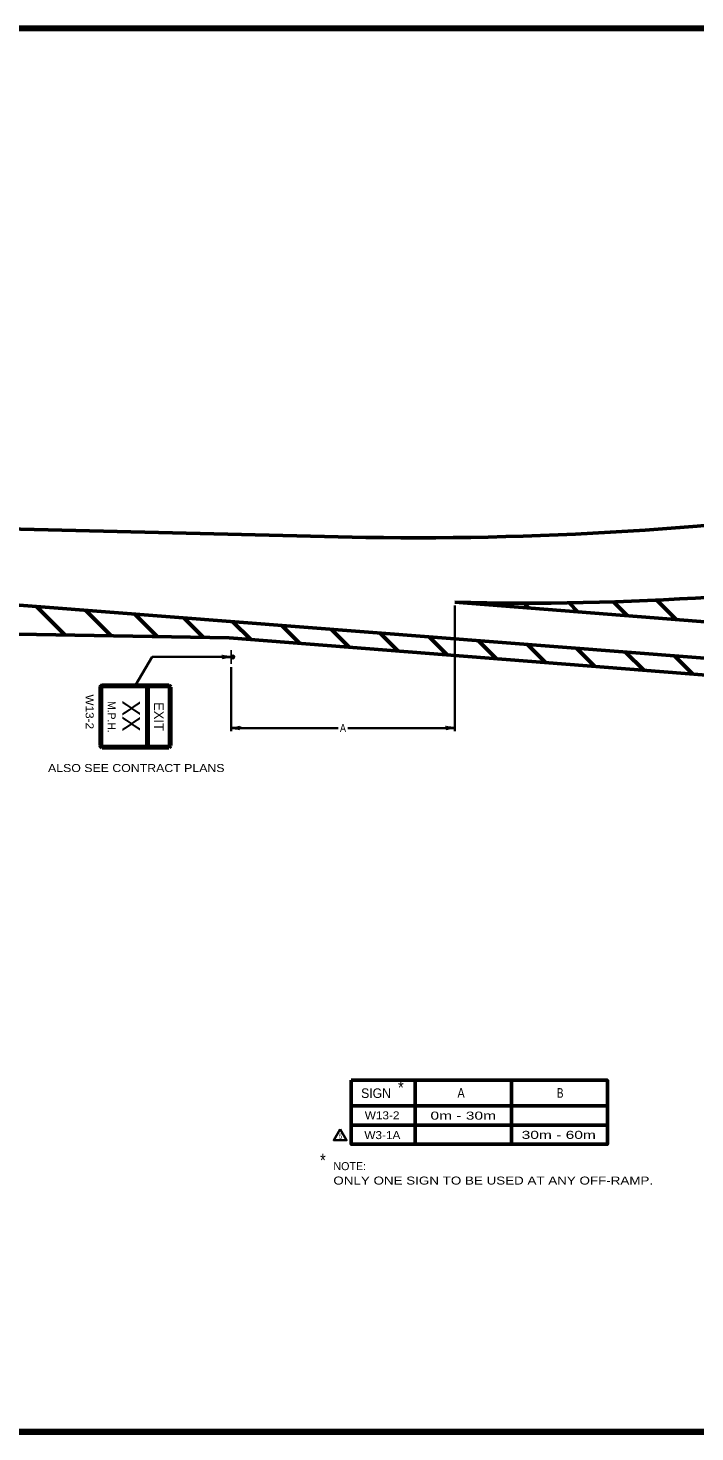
# Model space of a CAD drawing. Extents: x -371 to 484, y -338 to 206.
# Drawn here: x -83 to 167, y -326 to 200 of the extents above; entities that cross this region are included whole.
import ezdxf
from ezdxf.enums import TextEntityAlignment as Align

# ---------------------------------------------------------------- set-up
doc = ezdxf.new("R2010")
doc.units = 0
doc.layers.add('1', color=7, linetype='Continuous', lineweight=53)
doc.layers.add('4', color=7, linetype='Continuous', lineweight=25)
doc.layers.add('2', color=7, linetype='Continuous')

msp = doc.modelspace()

# ---------------------------------------------------------------- hatches: boundary and pattern name
at = {"layer": '4'}
msp.add_hatch(color=256, dxfattribs=at).paths.add_polyline_path([(-6.38, -36.735, 1), (-6.38, -35.423, 1)])

# ---------------------------------------------------------------- linework, layer by layer
at = {"layer": '1'}
for p, q in [((-288.756, 16.515), (43.484, 8.747)), ((76.814, -15.591), (456.428, -45.449)), ((86.227, -16.332), (85.575, -15.679)), ((123.066, -19.229), (119.501, -15.664)), ((141.485, -20.678), (136.155, -15.347)), ((159.905, -22.127), (152.429, -14.65)), ((-69.234, -27.852), (-79.901, -17.185)), ((-51.961, -28.155), (-61.511, -18.605)), ((-34.687, -28.457), (-43.12, -20.024)), ((104.647, -17.78), (102.717, -15.85)), ((-17.414, -28.76), (-24.73, -21.444)), ((0.361, -29.565), (-6.34, -22.863)), ((18.771, -31.004), (12.05, -24.283)), ((37.181, -32.443), (30.44, -25.703)), ((55.591, -33.882), (48.831, -27.122)), ((74, -35.321), (67.221, -28.542)), ((92.41, -36.761), (85.611, -29.962)), ((110.82, -38.2), (104.001, -31.381)), ((129.23, -39.639), (122.391, -32.801)), ((147.639, -41.078), (140.781, -34.22)), ((166.049, -42.517), (159.172, -35.64)), ((61.998, -218.715), (61.998, -194.715)), ((97.998, -218.715), (97.998, -194.715)), ((37.998, -204.315), (133.998, -204.315)), ((37.998, -211.514), (133.998, -211.514))]:
    msp.add_line(p, q, dxfattribs=at)
at = {"layer": '1', "lineweight": 35}
for p, q in [((76.814, -16.791), (76.814, -63.9)), ((-42.878, -46.653), (-36.641, -36.079)), ((-7.02, -36.079), (-36.641, -36.079)), ((-7.02, -39.839), (-7.02, -63.9)), ((-7.02, -62.7), (33.097, -62.7)), ((36.697, -62.7), (76.814, -62.7))]:
    msp.add_line(p, q, dxfattribs=at)
at = {"layer": '1', "lineweight": 13}
for p, q in [((-56.038, -69.464), (-56.038, -47.238)), ((-55.512, -46.653), (-30.243, -46.653)), ((-29.717, -47.238), (-29.717, -69.464)), ((-30.243, -70.049), (-55.512, -70.049))]:
    msp.add_line(p, q, dxfattribs=at)
at = {"layer": '1', "lineweight": 70}
for p, q in [((-55.358, -46.872), (-30.397, -46.872)), ((-38.349, -46.872), (-38.349, -69.83)), ((-55.841, -69.294), (-55.841, -47.408)), ((-29.914, -47.408), (-29.914, -69.294)), ((-30.397, -69.83), (-55.358, -69.83))]:
    msp.add_line(p, q, dxfattribs=at)
at = {"layer": '1', "lineweight": 158}
msp.add_line((477.495, -326.494), (-314.105, -326.494), dxfattribs=at)
msp.add_lwpolyline([(477.495, 199.606), (-314.205, 199.506), (-314.105, -326.494)], dxfattribs=at)
at = {"layer": '1'}
for points in [[(-289.357, -11.407), (-102.62, -15.431), (458.068, -58.713)], [(460.106, -65.505), (-7.77, -28.929), (-289.578, -23.989)]]:
    msp.add_lwpolyline(points, dxfattribs=at)
msp.add_lwpolyline([(37.998, -194.715), (133.998, -194.715), (133.998, -218.715), (37.998, -218.715)], close=True, dxfattribs=at)
at = {"layer": '1', "lineweight": 35}
msp.add_lwpolyline([(33.875, -213.023), (31.475, -217.18), (36.275, -217.18)], close=True, dxfattribs=at)
at = {"layer": '1'}
for centre, radius, start, end in [((62.954, 1263.937), 1255.341, 269.11133, 288.21006), ((102.852, 1063.378), 1079.284, 268.61761, 289.03246)]:
    msp.add_arc(centre, radius, start, end, dxfattribs=at)
at = {"layer": '1', "lineweight": 40}
for centre, major_axis, ratio, start_param, end_param in [((-8.329, -36.411), (2.143, 0.187), 0.122415, 0.8963533, 3.1415927), ((-8.365, -35.825), (2.108, -0.211), 0.07063, 3.1407148, 5.41811), ((-5.675, -62.954), (-2.108, 0.211), 0.07063, 3.1407148, 5.41811), ((-5.675, -62.954), (-2.108, 0.211), 0.07063, 3.1407148, 5.41811), ((-5.71, -62.368), (-2.143, -0.187), 0.122415, 0.8963533, 3.1415927), ((-5.71, -62.368), (-2.143, -0.187), 0.122415, 0.8963533, 3.1415927), ((75.505, -63.032), (2.143, 0.187), 0.122415, 0.8963533, 3.1415927), ((75.469, -62.446), (2.108, -0.211), 0.07063, 3.1407148, 5.41811)]:
    msp.add_ellipse(centre, major_axis=major_axis, ratio=ratio, start_param=start_param, end_param=end_param, dxfattribs=at)
at = {"layer": '1', "lineweight": 13}
for centre, major_axis, start_param, end_param in [((-55.512, -47.237), (0, 0.585), 6.2831853, 7.8539816), ((-30.243, -47.237), (0, 0.585), 4.712389, 6.2831853), ((-55.512, -69.464), (0, -0.585), 4.712389, 6.2831853), ((-30.243, -69.464), (0, 0.585), 3.1415927, 4.712389)]:
    msp.add_ellipse(centre, major_axis=major_axis, ratio=0.9, start_param=start_param, end_param=end_param, dxfattribs=at)
at = {"layer": '1', "lineweight": 70}
for centre, major_axis, start_param, end_param in [((-55.358, -47.408), (0, 0.536), 6.2831853, 7.8539816), ((-30.397, -47.408), (0, 0.536), 4.712389, 6.2831853), ((-55.358, -69.294), (0, -0.536), 4.712389, 6.2831853), ((-30.397, -69.294), (0, 0.536), 3.1415927, 4.712389)]:
    msp.add_ellipse(centre, major_axis=major_axis, ratio=0.9, start_param=start_param, end_param=end_param, dxfattribs=at)
at = {"layer": '4'}
msp.add_line((-7.02, -33.519), (-7.02, -38.639), dxfattribs=at)
msp.add_circle((-6.38, -36.079), 0.656, dxfattribs=at)

# ---------------------------------------------------------------- texts
at = {"layer": '1'}
for s, height, p in [('XX', 6.534, (-47.723, -58.186)), ('M.P.H.', 2.904, (-53.212, -58.542)), ('EXIT', 3.63, (-35.885, -58.396))]:
    msp.add_text(s, height=height, rotation=270, dxfattribs=at).set_placement(p, align=Align.CENTER)
msp.add_text('35', height=0.0183, rotation=269.642, dxfattribs=at).set_placement((-39.458, -54.94))
for s, height, width, p in [('A', 3, 0.85, (34.897, -64.2)), ('ALSO SEE CONTRACT PLANS', 3, 1.15, (-42.554, -79.202)), ('SIGN', 3.6, 0.95, (47.283, -201.35)), ('*', 4.8, 0.85, (56.596, -199.849)), ('A', 3.6, 0.85, (79.148, -201.258)), ('B', 3.6, 0.75, (116.309, -201.258)), ('W13-2', 3, 1.1, (49.565, -209.361)), ('0m - 30m', 3, 1.45, (79.97, -209.453)), ('W3-1A', 3, 1.1, (49.657, -216.759)), ('30m - 60m', 3, 1.45, (115.761, -216.668)), ('*', 4.8, 0.85, (27.378, -227.067))]:
    msp.add_text(s, height=height, dxfattribs=dict(at, width=width)).set_placement(p, align=Align.CENTER)
for s, height, width, p in [('5', 1.8, 0.9, (33.303, -216.579)), ('ONLY ONE SIGN TO BE USED AT ANY OFF-RAMP.', 3, 1.25, (31.305, -233.797))]:
    msp.add_text(s, height=height, dxfattribs=dict(at, width=width)).set_placement(p)
msp.add_text('NOTE:', height=3, dxfattribs=at).set_placement((31.305, -228.397))
at = {"layer": '2', "width": 1.1}
msp.add_text('W13-2', height=3, rotation=270, dxfattribs=at).set_placement((-61.514, -56.611), align=Align.CENTER)

doc.saveas('drawing.dxf')
